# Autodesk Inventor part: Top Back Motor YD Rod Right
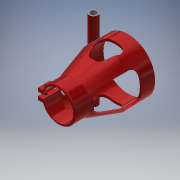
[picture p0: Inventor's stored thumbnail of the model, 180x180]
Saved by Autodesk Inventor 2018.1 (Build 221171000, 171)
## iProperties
Created: 2018-06
Part Number: Top Back Motor YD Rod Right
Material: Generic
Document SubType Name: Modeling
Designer: Ryan
Density: 1 g/cm^3
Appearance: Default
Author: Ryan
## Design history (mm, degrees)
derived "Assembly3 Part out.iam"
sketch "Sketch1"
  geometry: L1 (-38.527, 77.015)-(136.232, 77.015); L2 (136.232, 77.015)-(136.232, -217.058); L3 (136.232, -217.058)-(-38.527, -217.058); L4 (-38.527, -217.058)-(-38.527, 77.015); 1 further point
  constraints: 8 end point, 2 parallel, 1 horizontal, 1 perpendicular
extrude "Extrusion1" cut sketch "Sketch1" distance "d1" = 25.4; taper "d2" = 0 deg
workplane "Work Plane2"
  workplane "Work Plane1"
workpoint "Work Point1"
workplane "Work Plane3"
workplane "Work Plane4"
workplane "Work Plane5"
workplane "Work Plane6"
workplane "Work Plane7"
workplane "Work Plane8"
workplane "Work Plane9"
workplane "Work Plane10"
workplane "Work Plane11"
workplane "Work Plane12"
sketch "Sketch2"
  geometry: L1 (-120.064, -229.344)-(13.991, -229.344); L2 (13.991, -229.344)-(13.991, 75.966); L3 (13.991, 75.966)-(-120.064, 75.966); L4 (-120.064, 75.966)-(-120.064, -229.344); 1 further point
  constraints: 8 end point, 2 parallel, 1 horizontal, 1 perpendicular
extrude "Extrusion2" cut sketch "Sketch2" distance "d10" = 25.4; taper "d11" = 0 deg
sketch "Sketch3"
  geometry: C1 r 103.315 at (-49.509, 32.992); 1 further point
  constraints: 1 centre point
extrude "Extrusion3" cut sketch "Sketch3" distance "d12" = 106.3625; taper "d13" = 0 deg
sketch "Sketch4"
  geometry: C1 r 4.763 at (0, 0) reference; C2 r 3.429 at (0, 0); C3 r 4.763 at (101.6, 0) reference; C4 r 3.429 at (101.6, 0); 1 further point
  constraints: 2 centre point, 2 coincident
  dimensions: "d14" = 6.858 diameter of C2; "d15" = 6.858 diameter of C4
extrude "Extrusion4" cut sketch "Sketch4" distance "d16" = 12.7; taper "d17" = 0 deg
sketch "Sketch5"
  geometry: C1 r 4.763 at (0, 0) reference; C2 r 3.429 at (0, 0); C3 r 4.763 at (-101.6, 0) reference; C4 r 3.429 at (-101.6, 0); 1 further point
  constraints: 2 centre point, 2 coincident
  dimensions: "d18" = 6.858 diameter of C2; "d19" = 6.858 diameter of C4
extrude "Extrusion5" cut sketch "Sketch5" distance "d20" = 15.875; taper "d21" = 0 deg
sketch "Sketch8"
  geometry: L1 (-67.872, 56.19)-(75.537, 56.19); L2 (75.537, 56.19)-(75.537, -71.664); L3 (75.537, -71.664)-(-67.872, -71.664); L4 (-67.872, -71.664)-(-67.872, 56.19); 1 further point
  constraints: 8 end point, 2 parallel, 1 horizontal, 1 perpendicular
extrude "Extrusion6" cut sketch "Sketch8" distance "d22" = 176.2125; taper "d23" = 0 deg
sketch "Sketch9"
  geometry: C1 r 3.429 at (0, 0) reference; C2 r 3.429 at (0, 0); C3 r 4.763 at (0, 0); 1 further point
  constraints: 2 centre point, 2 coincident
extrude "Extrusion7" join sketch "Sketch9" distance "d24" = 9.525; taper "d25" = 0 deg
body "Solid1"
node "Rov v4.2.ipt:1" dims "d0" = 10
node "Motor mount.ipt:1" dims "d0" = 10
node "Motor mount.ipt:2" dims "d0" = 10
node "Motor mount_MIR2.ipt:1" dims "d0" = 10
other parameters: "d3" = 6.35, "d4" = 12.7, "d5" = -12.7, "d6" = 12.7, "d7" = -12.7, "d8" = 6.35, "d9" = -6.35
